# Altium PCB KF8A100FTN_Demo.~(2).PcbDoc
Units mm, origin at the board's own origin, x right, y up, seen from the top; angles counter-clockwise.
Board outline 152.4 x 101.6 mm, 2 copper layers (Top Layer, Bottom Layer); 11 components, 0 nets, 73 pads, 0 vias.
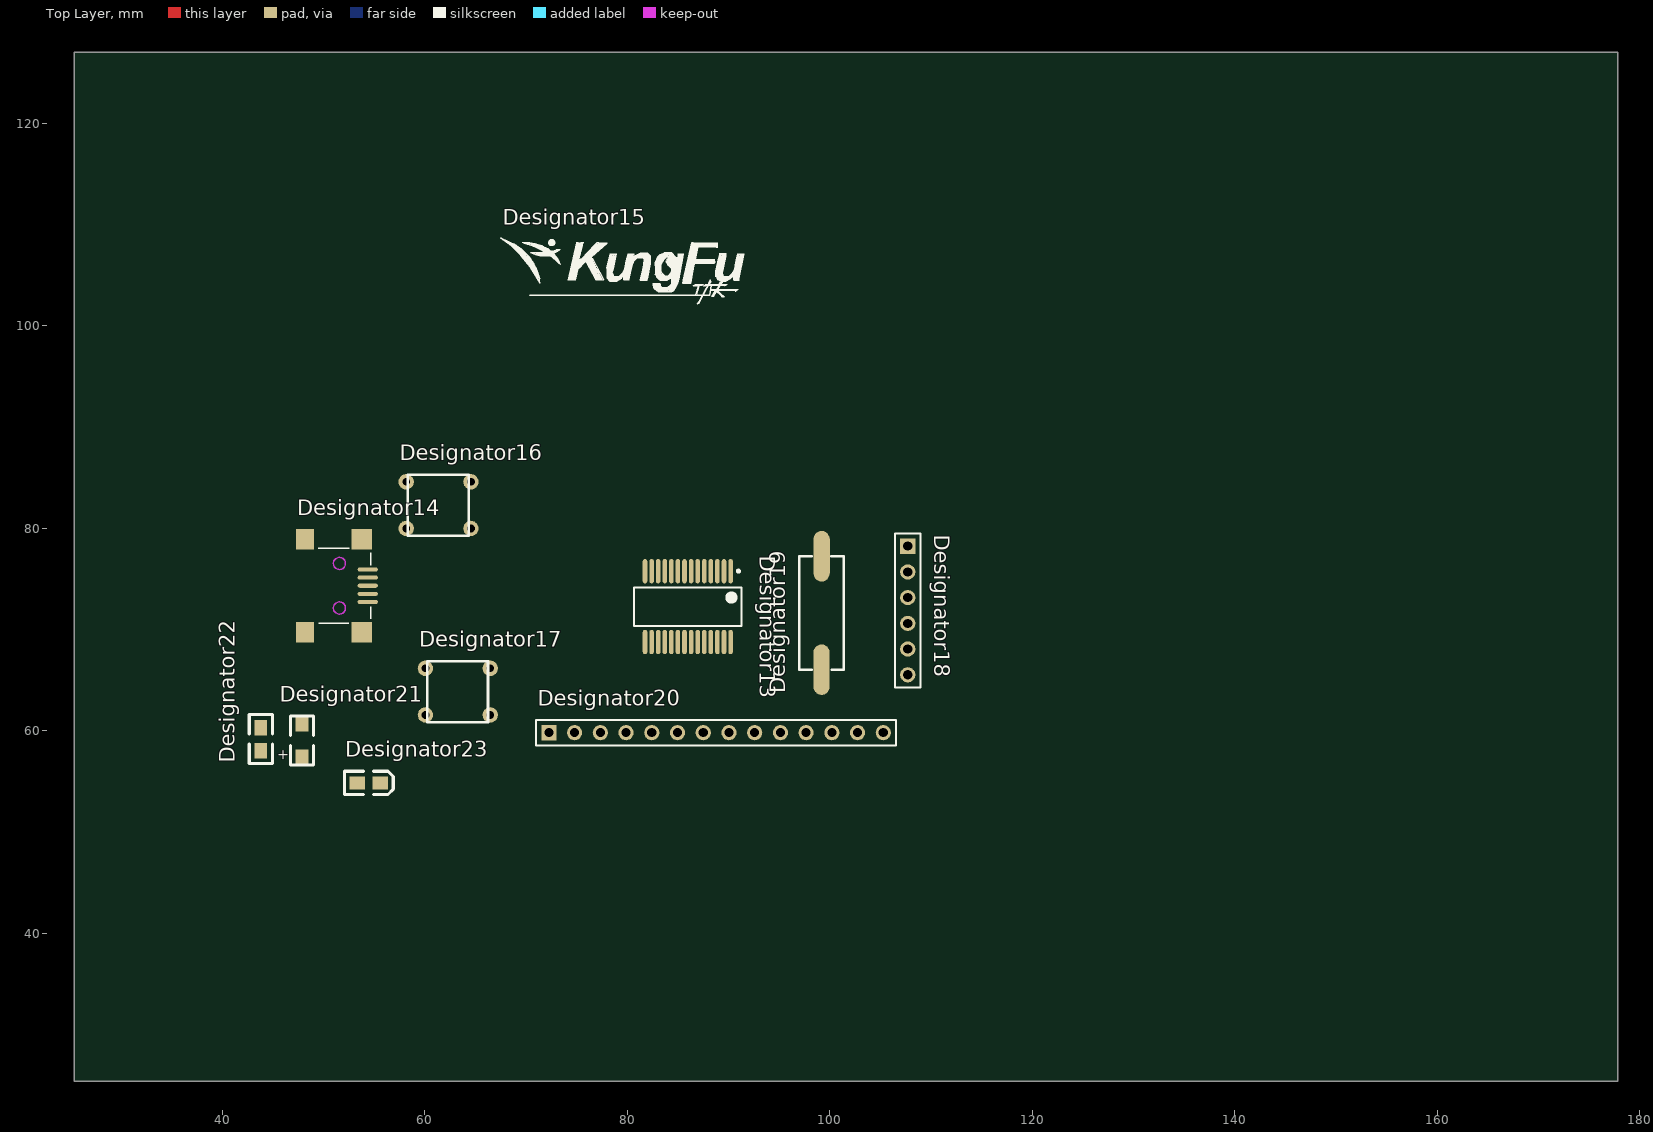
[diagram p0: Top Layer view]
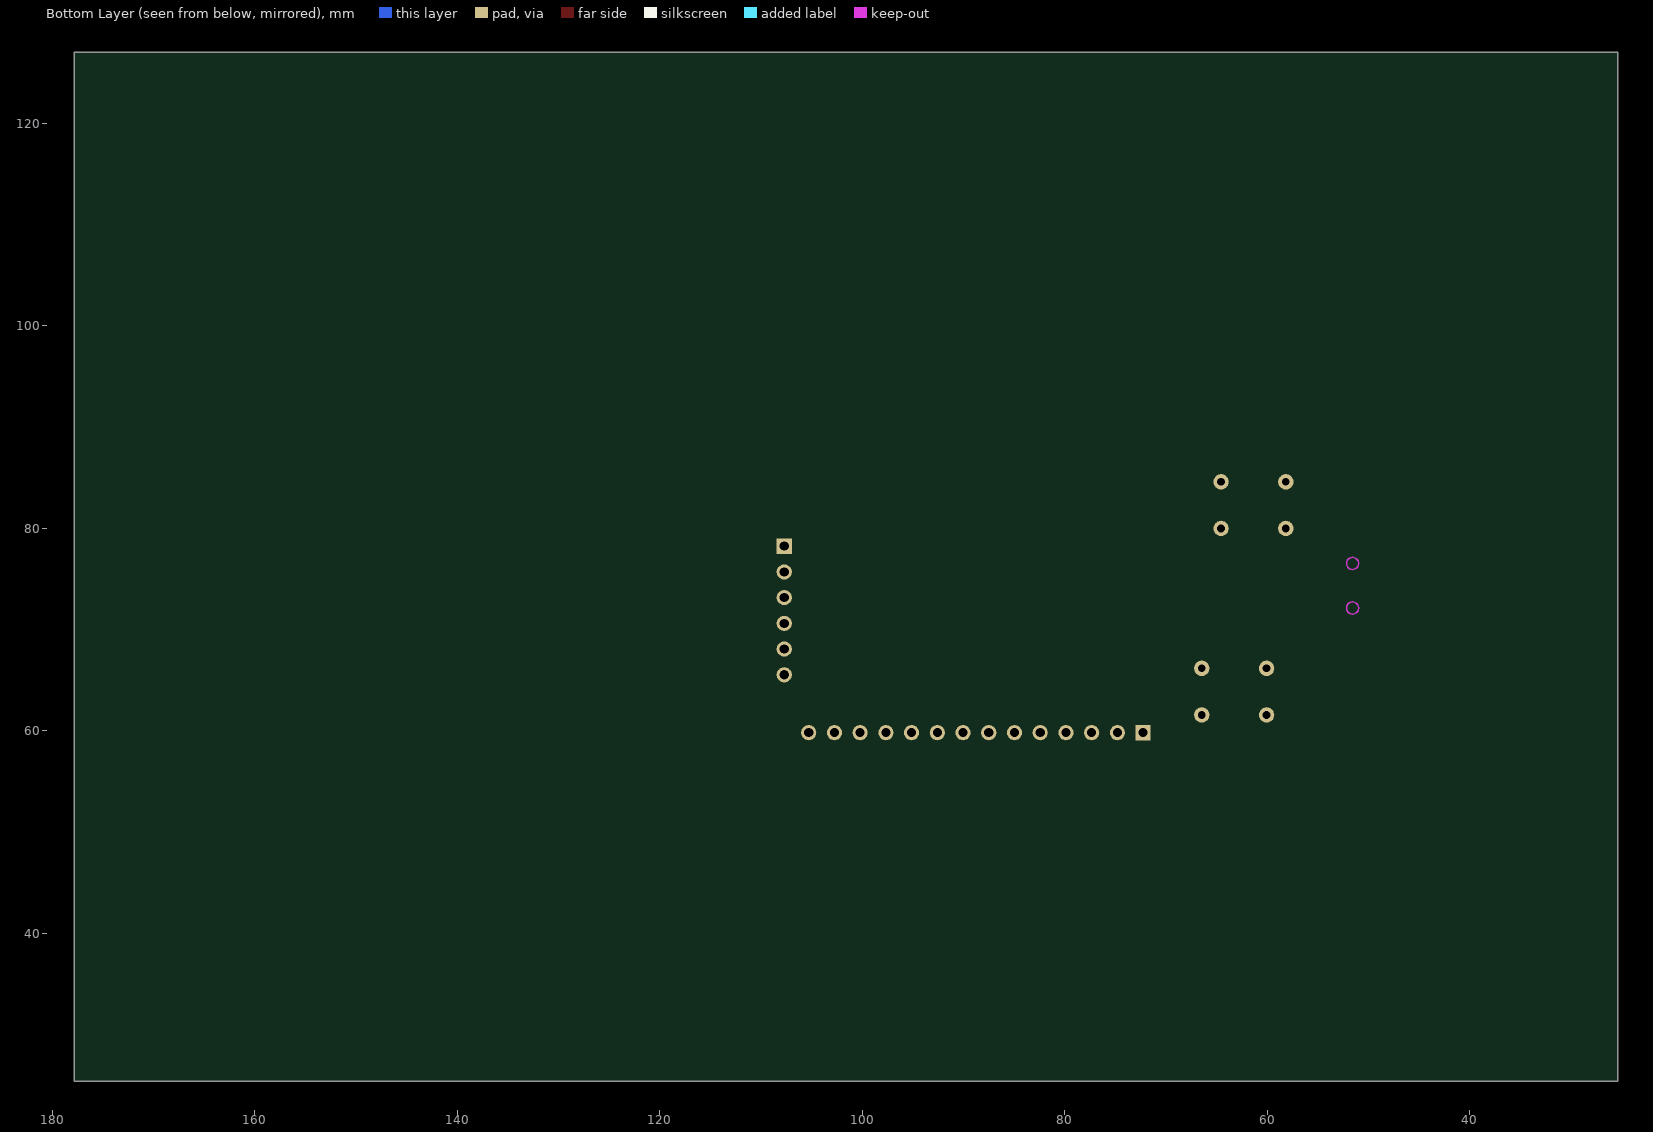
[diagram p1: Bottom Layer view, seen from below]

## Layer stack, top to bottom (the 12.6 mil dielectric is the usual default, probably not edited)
Top Solder: solder mask 0.0102, Solder Resist, Dk 3.5
Top Layer: signal copper 0.0356
Dielectric 1: dielectric 0.32, FR-4, Dk 4.8
Bottom Layer: signal copper 0.0356
Bottom Solder: solder mask 0.0102, Solder Resist, Dk 3.5

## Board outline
25.4,25.4 177.8,25.4 177.8,127 25.4,127

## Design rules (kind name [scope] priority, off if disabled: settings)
Clearance [All] p1: gap=0.254
PolygonConnect [All] p1: connectstyle=Relief reliefconductorwidth=0.254 reliefentries=4 polygonreliefangle="90 Angle" airgapwidth=0.254
RoutingVias [All] p1: holewidth=0.711 width=1.27 viastyle="Through Hole" minholewidth=0.711 minwidth=1.27 maxholewidth=0.711 maxwidth=1.27
SolderMaskExpansion [All] p1: expansion=0.102
UnpouredPolygon [All] p1: allowunpoured=FALSE
Width [All] p1: maxlimit=0.254 minlimit=0.254 preferedwidth=0.254
29 further rules are at their usual default settings.

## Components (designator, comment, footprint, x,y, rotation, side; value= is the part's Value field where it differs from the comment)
Designator13 "Comment" SSOP-SS28_M 85.979,72.263 r270 top
Designator14 "Comment" USB_MINI_B 51.435,75.184 r0 top
Designator15 "Comment" LOGO 70.358,102.997 r0 top
Designator16 "Comment" KEY6*6 58.166,84.582 r0 top
Designator17 "Comment" KEY6*6 60.071,66.167 r0 top
Designator18 "Comment" HDR1X6 107.696,78.232 r270 top
Designator19 "Comment" CRYSTAL 99.187,66.04 r90 top
Designator20 "Comment" HDR1X14 72.263,59.817 r0 top
Designator21 "Comment" 0805L 47.879,57.912 r0 top
Designator22 "Comment" 0805 43.815,58.039 r90 top
Designator23 "Comment" D0805 53.34,54.864 r0 top

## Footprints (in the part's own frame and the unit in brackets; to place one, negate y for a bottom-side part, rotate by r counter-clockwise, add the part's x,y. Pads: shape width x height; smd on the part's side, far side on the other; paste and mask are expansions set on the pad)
0805 [mil]
  rect 60x50 smd: 1(-0.11,0) 2(89.89,0)
  silkscreen extent -50,-45 140,45
0805L [mil]
  rect 50x60 smd: 1(0,-19.68) 2(0,109.68)
  silkscreen extent -45,-50 45,140
CRYSTAL [mm]
  oval 5x1.6 smd: 1(0,0) 2(11.2,-0.01)
  silkscreen extent 0,-2.2 11.2,2.2
D0805 [mil]
  rect 60x50 smd: 1(0,0) 2(90,0)
  silkscreen extent -50,-45 140,45
HDR1X6 [mm] "Connector; Header; 6 Position"
  rect 1.5x1.5 hole 0.9: 1(0,0)
  round 1.5 hole 0.9: 2(2.54,0) 3(5.08,0) 4(7.62,0) 5(10.16,0) 6(12.7,0)
  silkscreen extent -1.27,-1.27 13.97,1.27
HDR1X14 [mm] "Connector; Header; 14 Position"
  rect 1.5x1.5 hole 0.9: 1(0,0)
  round 1.5 hole 0.9: 2(2.54,0) 3(5.08,0) 4(7.62,0) 5(10.16,0) 6(12.7,0) 7(15.24,0) 8(17.78,0) 9(20.32,0) 10(22.86,0) 11(25.4,0) 12(27.94,0) 13(30.48,0) 14(33.02,0)
  silkscreen extent -1.27,-1.27 34.29,1.27
KEY6*6 [mil]
  round 60 hole 30: 1(0,0) 2(0,-181.1) 3(251.97,0) 4(251.97,-181.1)
  silkscreen extent 7,-209 243,28
LOGO [mm]
  silkscreen extent -2.9,-0.84 21.21,5.71
SSOP-SS28_M [mm] "SOP, 28-Leads, Body 10.2x5.2mm, Pitch 0.65mm, IPC Low Density"
  oval 2.4x0.45 smd: 1(-3.5,4.225) 2(-3.5,3.575) 3(-3.5,2.925) 4(-3.5,2.275) 5(-3.5,1.625) 6(-3.5,0.975) 7(-3.5,0.325) 8(-3.5,-0.325) 9(-3.5,-0.975) 10(-3.5,-1.625) 11(-3.5,-2.275) 12(-3.5,-2.925) 13(-3.5,-3.575) 14(-3.5,-4.225) 15(3.5,-4.225) 16(3.5,-3.575) 17(3.5,-2.925) 18(3.5,-2.275) 19(3.5,-1.625) 20(3.5,-0.975) 21(3.5,-0.325) 22(3.5,0.325) 23(3.5,0.975) 24(3.5,1.625) 25(3.5,2.275) 26(3.5,2.925) 27(3.5,3.575) 28(3.5,4.225)
  silkscreen extent -3.62,-5.3 1.9,5.3, body extent -2.7,-5.3 2.7,5.3, height 2
USB_MINI_B [mm] "USB_MINI_B"
  oval 2x0.4 smd: 1(2.941,0.744) 2(2.941,-0.056) 3(2.941,-0.856) 4(2.941,-1.656) 5(2.941,-2.456)
  rect 1.797x2 smd: 6(-3.259,-5.456) 6(-3.259,3.744)
  rect 2x2 smd: 6(2.341,-5.456) 6(2.341,3.744)
  Keep-Out Layer circle w0.127: c0.141,1.344 r0.6
  Keep-Out Layer circle w0.127: c0.141,-3.056 r0.6
  silkscreen extent -1.93,-4.58 3.24,2.85

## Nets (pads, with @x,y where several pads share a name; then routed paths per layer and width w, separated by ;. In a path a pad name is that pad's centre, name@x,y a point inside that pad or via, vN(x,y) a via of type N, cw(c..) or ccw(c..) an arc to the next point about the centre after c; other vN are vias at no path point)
pads on no net: Designator13.1 Designator13.2 Designator13.3 Designator13.4 Designator13.5 Designator13.6 Designator13.7 Designator13.8 Designator13.9 Designator13.10 Designator13.11 Designator13.12 Designator13.13 Designator13.14 Designator13.15 Designator13.16 Designator13.17 Designator13.18 Designator13.19 Designator13.20 Designator13.21 Designator13.22 Designator13.23 Designator13.24 Designator13.25 Designator13.26 Designator13.27 Designator13.28 Designator14.1 Designator14.2 Designator14.3 Designator14.4 Designator14.5 Designator14.6 Designator16.1 Designator16.2 Designator16.3 Designator16.4 Designator17.1 Designator17.2 Designator17.3 Designator17.4 Designator18.1 Designator18.2 Designator18.3 Designator18.4 Designator18.5 Designator18.6 Designator19.1 Designator19.2 Designator20.1 Designator20.2 Designator20.3 Designator20.4 Designator20.5 Designator20.6 Designator20.7 Designator20.8 Designator20.9 Designator20.10 Designator20.11 Designator20.12 Designator20.13 Designator20.14 Designator21.1 Designator21.2 Designator22.1 Designator22.2 Designator23.1 Designator23.2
